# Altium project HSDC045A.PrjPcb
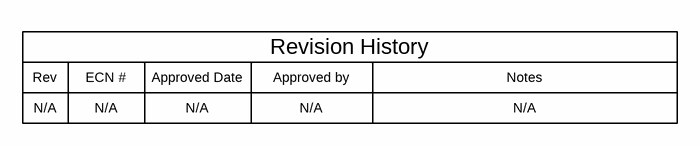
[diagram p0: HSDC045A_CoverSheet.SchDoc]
TID: N/A; TechSupport: https://e2e.ti.com/support/interface/ethernet/; SCH_Rev: A; PRJ_Title: DP83825EVM; PRJ_Number: HSDC045; PRJ_Engineer: Aniruddha Khadye; PRJ_Customer: Public Release; PCB_Rev: A; PCB_Layout: TBD; CopyrightYear: 2018
5 sheets, 159 parts. Net scope: global (net labels, ports and power ports of the same name join across sheets).
Board file: HSDC045A.PcbDoc
Sheets:
  HSDC045A_CoverSheet.SchDoc
  HSDC045A_Power.SchDoc
  HSDC045A_DP83825.SchDoc
  HSDC045A_Coms.SchDoc
  HSDC045A_Hardware.SchDoc

## Sheet HSDC045A_CoverSheet.SchDoc: Block Diagram
size 431 x 279 mm; Date: Not shown in title block; ApprovedBy: Not shown in title block; CheckedBy: Not shown in title block; Author: Not shown in title block; CompanyName: Not shown in title block; DrawnBy: Aniruddha Khadye; Engineer: Not shown in title block; Organization: Not shown in title block; Address1: Not shown in title block; Address2: Not shown in title block; Address3: Not shown in title block; Address4: Not shown in title block; DocumentNumber: 1; Revision: Use project parameter SCH_Rev; SheetNumber: 1; SheetTotal: 5; PageSetup: Record=PageOptions¦CenterHorizontal=True¦CenterVertical=True¦PrintScale=1.00¦XCorrection=1.00¦YCorrection=1.00¦PrintKind=0¦BorderSize=5000000¦LeftOffset=0¦BottomOffset=0¦Orientation=2¦PaperLength=1000¦PaperWidth=1000¦Scale=100¦PaperSource=15¦PrintQuality=600¦MediaType=1¦DitherType=10¦PaperKind=Letter¦PrintScaleMode=1

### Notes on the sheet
- Rev
- N/A
- ECN #
- Approved Date
- Approved by
- Revision History
- Notes

## Sheet HSDC045A_Power.SchDoc
size 431 x 279 mm; Date: Not shown in title block; ApprovedBy: Not shown in title block; CheckedBy: Not shown in title block; Author: Not shown in title block; CompanyName: Not shown in title block; Engineer: Not shown in title block; Organization: Not shown in title block; Address1: Not shown in title block; Address2: Not shown in title block; Address3: Not shown in title block; Address4: Not shown in title block; DocumentNumber: 2; Revision: Use project parameter SCH_Rev; SheetNumber: 2; SheetTotal: 5; PageSetup: Record=PageOptions¦CenterHorizontal=True¦CenterVertical=True¦PrintScale=1.00¦XCorrection=1.00¦YCorrection=1.00¦PrintKind=0¦BorderSize=5000000¦LeftOffset=0¦BottomOffset=0¦Orientation=2¦PaperLength=1000¦PaperWidth=1000¦Scale=100¦PaperSource=15¦PrintQuality=600¦MediaType=1¦DitherType=10¦PaperKind=Letter¦PrintScaleMode=1
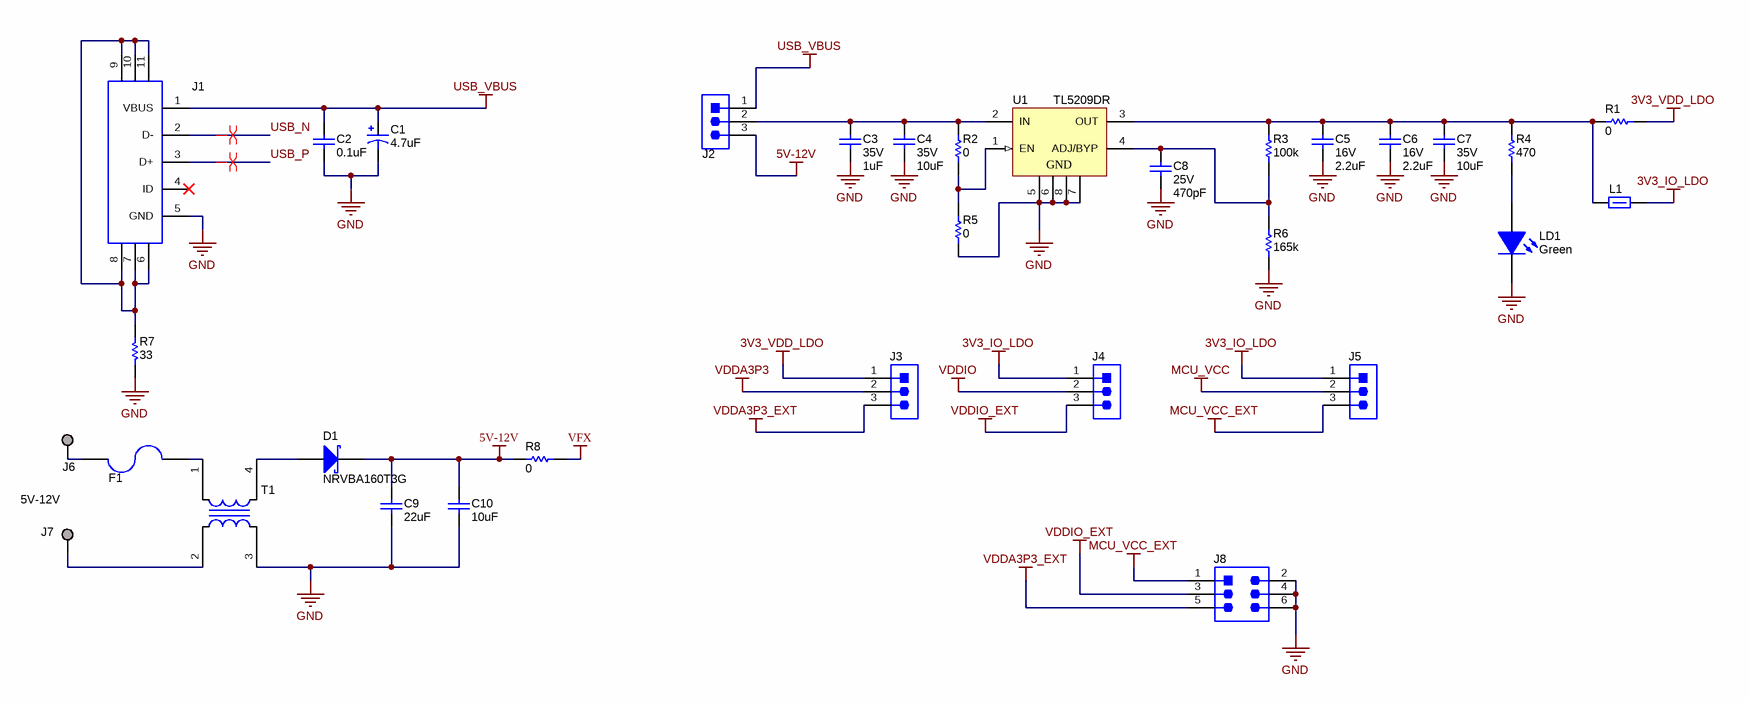
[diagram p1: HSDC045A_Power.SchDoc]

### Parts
C1  ValueDisplayed: 4.7uF  [7343-31]  (hidden comment: 293D475X9035D2TE3)
C2  ValueDisplayed: 0.1uF  [0402]  (hidden comment: GRM155R71C104KA88D)
C3  VDC_V: 35V  ValueDisplayed: 1uF  [0402]  (hidden comment: GRM155R6YA105ME11D)
C4  VDC_V: 35V  ValueDisplayed: 10uF  [0603]  (hidden comment: GRM188R6YA106MA73)
C5  VDC_V: 16V  ValueDisplayed: 2.2uF  [0402]  (hidden comment: GRM155C81C225KE11D)
C6  VDC_V: 16V  ValueDisplayed: 2.2uF  [0402]  (hidden comment: GRM155C81C225KE11D)
C7  VDC_V: 35V  ValueDisplayed: 10uF  [0603]  (hidden comment: GRM188R6YA106MA73)
C8  VDC_V: 25V  ValueDisplayed: 470pF  [0402]  (hidden comment: GRM1555C1E471JA01D)
C9  ValueDisplayed: 22uF  [1210_280]  (hidden comment: CGA6P1X7R1C226M250AC)
C10  ValueDisplayed: 10uF  [1210_280]  (hidden comment: CGA6P1X7R1E106M250AC)
D1  NRVBA160T3G  [SMA]
F1  F0603E3R00FSTR  [0603]  (value not drawn)
J1  475890001  [Molex_0475890001]  (value not drawn)
J2  PEC03SAAN  [CONN_PEC03SAAN]  (value not drawn)
J3  PEC03SAAN  [CONN_PEC03SAAN]  (value not drawn)
J4  PEC03SAAN  [CONN_PEC03SAAN]  (value not drawn)
J5  PEC03SAAN  [CONN_PEC03SAAN]  (value not drawn)
J6  1502-2  [Keystone1502-2]  (value not drawn)
J7  1502-2  [Keystone1502-2]  (value not drawn)
J8  5-146254-3  [TE_5-146254-3]  (value not drawn)
L1  BLM18AG102SN1D  [0603]  (value not drawn)
LD1  value Green  [QTLP630C_Green]  (hidden comment: QTLP630C4TR)
R1  ValueDisplayed: 0  [0603]  (hidden comment: ERJ-3GEY0R00V)
R2  ValueDisplayed: 0  [0603]  (hidden comment: ERJ-3GEY0R00V)
R3  ValueDisplayed: 100k  [0402]  (hidden comment: CRCW0402100KDHEDP)
R4  ValueDisplayed: 470  [0402]  (hidden comment: CRCW0402470RJNED)
R5  ValueDisplayed: 0  [0603]  (hidden comment: ERJ-3GEY0R00V)
R6  ValueDisplayed: 165k  [0402]  (hidden comment: CRCW0402165KFKED)
R7  ValueDisplayed: 33  [0402]  (hidden comment: CRCW040233R0JNED)
R8  ValueDisplayed: 0  [0402]  (hidden comment: MCR01MZPJ000)
T1  ACM9070-701-2PL-TL01  [TDK_ACM9070]  (value not drawn)
U1  TL5209DR  [D0008A_N]

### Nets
3V3_IO_LDO: J4.1 J5.1 L1.2
3V3_VDD_LDO: J3.1 R1.2
5V-12V: C9.1 C10.1 D1.1(K) J2.3 R8.2
GND: C1.2(-) C2.1 C3.2 C4.2 C5.2 C6.2 C7.2 C8.2 C9.2 C10.2 J1.5(GND) J8.2 J8.4 J8.6 LD1.2(K) R5.1 R6.1 R7.2 T1.3 U1.5(GND) U1.6(GND) U1.7(GND) U1.8(GND)
MCU_VCC: J5.2
MCU_VCC_EXT: J5.3 J8.1
USB_VBUS: C1.1(+) C2.2 J1.1(VBUS) J2.1
VDDA3P3: J3.2
VDDA3P3_EXT: J3.3 J8.5
VDDIO: J4.2
VDDIO_EXT: J4.3 J8.3
VFX: R8.1
USB_N: J1.2(D-)
USB_P: J1.3(D+)
NetC3_1: C3.1 C4.1 J2.2 R2.2 U1.2(IN)
NetC5_1: C5.1 C6.1 C7.1 L1.1 R1.1 R3.2 R4.2 U1.3(OUT)
NetC8_1: C8.1 R3.1 R6.2 U1.4(ADJ/BYP)
NetD1_2: D1.2(A) T1.4
NetF1_1: F1.1 J6.1
NetF1_2: F1.2 T1.1
NetJ1_6: J1.6 J1.7 J1.8 J1.9 J1.10 J1.11 R7.1
NetJ7_1: J7.1 T1.2
NetLD1_1: LD1.1(A) R4.1
NetR2_1: R2.1 R5.2 U1.1(EN)

Not connected (* = marked no-connect by the designer): J1 4(ID)*

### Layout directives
differential pair: USB_N, USB_P

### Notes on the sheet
- 5V-12V

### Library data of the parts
C1 = CMP-0011708-2: CAP, TA, 4.7 uF, 35 V, +/- 10%, 1.3 ohm, SMD; Manufacturer: Vishay-Sprague; Polarized: Y; CompType: Capacitor; Value: 4.7uF; U/M: EA; Cap_F: 4.7µF; Value1: 1.3 ohm; VDC_V: 35V; ESR_ohm: 1.3; IRMS_A: 3.4dA; TaMin_C: -55°C; TaMax_C: 125°C; Cap_Case: D; AEC Category: Q200; SizeAreaWB_mm2: 58.59; SizeArea_mm2: 31.39; SizeX_mm: 7.3; SizeY_mm: 4.3; SizeZ_mm: 3.1
C2 = CMP-0006641-2: CAP, CERM, 0.1 uF, 16 V, +/- 10%, X7R, 0402; Manufacturer: MuRata; Polarized: N; Value: 0.1uF; U/M: EA; Cap_F: 100nF; Value1: Unknown; VDC_V: 16V; TaMin_C: -55°C; TaMax_C: 125°C; AEC Category: Q200; SizeArea_mm2: 0.5; SizeAreaWB_mm2: 3; SizeX_mm: 1; SizeZ_mm: 0.6
C3 = CMP-0006620-2: CAP, CERM, 1 uF, 35 V, +/- 20%, X5R, 0402; Manufacturer: MuRata; TaMin_C: -55°C; Polarized: N; SizeAreaWB_mm2: 3; Value1: Unknown; U/M: EA; Value: 1uF; TaMax_C: 85°C; SizeZ_mm: 0.6; SizeX_mm: 1; SizeY_mm: 0.5; Cap_F: 1µF; AEC Category: Q200
C4 C7 = CMP-0007355-5: CAP, CERM, 10 uF, 35 V, +/- 20%, X5R, 0603; Manufacturer: Nichicon; TaMin_C: -55°C; Polarized: N; SizeAreaWB_mm2: 4.68; Value1: Unknown; U/M: EA; Value: 10uF; TaMax_C: 85°C; SizeZ_mm: 1; SizeX_mm: 1.6; SizeY_mm: 0.8; SizeArea_mm2: 1.28; Cap_F: 10µF; AEC Category: Q200
C5 C6 = CMP-0006526-2: CAP, CERM, 2.2 uF, 16 V, +/- 10%, X6S, 0402; Manufacturer: MuRata; TaMin_C: -55°C; Polarized: N; SizeAreaWB_mm2: 3; Value1: Unknown; U/M: EA; Value: 2.2uF; TaMax_C: 105°C; SizeZ_mm: 0.6; SizeX_mm: 1; SizeY_mm: 0.5; Cap_F: 2.2µF; AEC Category: Q200
C8 = CMP-0006389-2: CAP, CERM, 470 pF, 25 V, +/- 5%, C0G/NP0, 0402; Manufacturer: MuRata; TaMin_C: -55°C; Polarized: N; SizeAreaWB_mm2: 3; Value1: Unknown; U/M: EA; Value: 470pF; TaMax_C: 125°C; SizeZ_mm: 0.6; SizeX_mm: 1; SizeY_mm: 0.5; AEC Category: Q200
C9 = CMP-0009154-2: CAP, CERM, 22 uF, 16 V, +/- 20%, X7R, AEC-Q200 Grade 1, 1210; Manufacturer: TDK; Polarized: N; Value: 22uF; U/M: EA; Cap_F: 22µF; ESR_ohm: 2.582m; Value1: 0.002582 ohm; VDC_V: 16V; IRMS_A: 4.57562A; TaMin_C: -55°C; TaMax_C: 125°C; AEC Category: Q200; AEC Qualified: Y; AEC Grade: 1; SizeArea_mm2: 8; SizeAreaWB_mm2: 14.7; SizeX_mm: 3.2; SizeY_mm: 2.5; SizeZ_mm: 2.8
C10 = CMP-0009155-2: CAP, CERM, 10 uF, 25 V, +/- 20%, X7R, AEC-Q200 Grade 1, 1210; Manufacturer: TDK; Polarized: N; Value: 10uF; U/M: EA; Cap_F: 10µF; Value1: Unknown; VDC_V: 25V; TaMin_C: -55°C; TaMax_C: 125°C; Cap_Case: 1210; AEC Category: Q200; AEC Qualified: Y; AEC Grade: 1; SizeArea_mm2: 8; SizeAreaWB_mm2: 14.7; SizeX_mm: 3.2; SizeY_mm: 2.5; SizeZ_mm: 2.8
D1 = CMP-0028762-1: Diode, Schottky, 60 V, 1 A, AEC-Q101, SMA; Manufacturer: ON Semiconductor; U/M: EA; Vf_V: 5.1dV; Value: 60V; Value1: 1A; Value2: 0.51V; TJmax_C: 150°C; AEC Category: Q101; AEC Qualified: Y; Green_Lifecycle: Active; Green_REACh: Passed; SizeArea_mm2: 16.3228; SizeAreaWB_mm2: 37.3428; SizeX_mm: 5.59; SizeY_mm: 2.92; SizeZ_mm: 2.87
F1 = CMP-0003588-3: Fuse, 3 A, 32 VDC, SMD; Manufacturer: AVX; VDC_V: 32V; Irating_A: 3A; Rtyp_Ohm: 0.03; SizeAreaWB_mm2: 4.68; SizeArea_mm2: 1.28; SizeX_mm: 1.6; SizeY_mm: 0.8; SizeZ_mm: 1
J1 = CMP-0055301-1: Connector, Receptacle, Micro-USB Type AB, R/A, Bottom Mount SMT; Manufacturer: Molex; CompType: USB; Gender: Female; CNHeader: FALSE; CT: TRUE; Green_Lifecycle: Active; Green_REACh: Passed
J2-J5 = CMP-0002338-1: Header, 100mil, 3x1, Tin, TH; Manufacturer: Sullins Connector Solutions; CNHeader: TRUE; Current_A: 3A; Green_Lifecycle: Not Set; Shrouded: N; Gender: Male; Green_REACh: Incomplete; Voltage_V: 1.8kV; Row_Count: 1; Pitch_mm: 2.54; CT: FALSE; Cert_UL: Y
J6 J7 = CMP-0055113-1: Terminal, Turret, TH, Double; Manufacturer: Keystone; CompType: Turret Terminal; CNHeader: FALSE; Green_Lifecycle: Active; Green_REACh: Passed
J8 = CMP-0054953-2: Header, 100mil, 3x2, Tin, TH; Manufacturer: TE Connectivity; Green_REACh: Passed; Green_Lifecycle: Active
L1 = CMP-0003343-2: Ferrite Bead, 1000 ohm @ 100 MHz, 0.4 A, 0603; Manufacturer: MuRata; ZTyp@100MHz_Ohm: 1k; SizeAreaWB_mm2: 4.68; DCR_ohm: 5d; Value1: 0.5 ohm; Imax_A: 4dA; SizeZ_mm: 1; SizeX_mm: 1.6; SizeY_mm: 0.8; Value2: 0.4A; SizeArea_mm2: 1.28
LD1 = CMP-0002917-1: LED, Green, SMD; Manufacturer: Everlight; Vf_V: 2.1V; Io_A: 20mA; Vr_V: 5V; Tjmax_C: 85°C; Value1: W; Angle: 140; U/M: EA
R1 R2 R5 = CMP-0025874-4: RES, 0, 5%, 0.1 W, AEC-Q200 Grade 0, 0603; Manufacturer: Panasonic; Power_W: 100mW; TempCo: 600 ppm/C; Value_Code: 0000; Value: 0; EIA_Code: E24; SizeX_mm: 1.6; SizeY_mm: 0.8; SizeZ_mm: 1; Value2: 0.1W; SizeArea_mm2: 1.28; AEC Qualified: Y; VDC_V: 50V; AEC Category: Q200; SizeAreaWB_mm2: 4.68
R3 = CMP-0026768-2: RES, 100 k, 0.5%, 0.063 W, AEC-Q200 Grade 0, 0402; Manufacturer: Vishay-Dale; Power_W: 63mW; TempCo: 50 ppm/C; Value: 100k; EIA_Code: E192; SizeX_mm: 1; SizeY_mm: 0.5; SizeZ_mm: 0.6; Value2: 0.063W; AEC Qualified: Y; VDC_V: 50V; AEC Category: Q200; AEC Grade: 0
R4 = CMP-0026934-3: RES, 470, 5%, 0.063 W, AEC-Q200 Grade 0, 0402; Manufacturer: Vishay-Dale; Power_W: 63mW; TempCo: 200 ppm/C; Value_Code: 470R; Value: 470; EIA_Code: E24; SizeX_mm: 1; SizeY_mm: 0.5; SizeZ_mm: 0.6; Value2: 0.063W; AEC Qualified: Y; VDC_V: 50V; AEC Category: Q200; AEC Grade: 0
R6 = CMP-0026036-3: RES, 165 k, 1%, 0.063 W, AEC-Q200 Grade 0, 0402; Manufacturer: Vishay-Dale; Power_W: 63mW; TempCo: 100 ppm/C; Value: 165k; EIA_Code: E96; SizeX_mm: 1; SizeY_mm: 0.5; SizeZ_mm: 0.6; Value2: 0.063W; AEC Qualified: Y; VDC_V: 50V; AEC Category: Q200; AEC Grade: 0
R7 = CMP-0026908-3: RES, 33, 5%, 0.063 W, AEC-Q200 Grade 0, 0402; Manufacturer: Vishay-Dale; Value: 33; Value_Code: 33R0; Power_W: 63mW; Value2: 0.063W; VDC_V: 50V; TempCo: 200 ppm/C; EIA_Code: E24; AEC Category: Q200; AEC Qualified: Y; AEC Grade: 0; SizeArea_mm2: 0.5; SizeX_mm: 1; SizeZ_mm: 0.6
R8 = CMP-0027002-2: RES, 0, 5%, 0.063 W, 0402; Manufacturer: Rohm; Power_W: 63mW; TempCo: 500 ppm/C; Value_Code: 0000; U/M: EA; Value: 0; EIA_Code: E24; SizeX_mm: 1; SizeY_mm: 0.5; SizeZ_mm: 0.6; Value2: 0.063W; VDC_V: 50V; AEC Category: Q200
T1 = CMP-0013076-2: Coupled inductor, 5 A, 0.01 ohm, SMD; Manufacturer: TDK; DCR_ohm: 0.01
U1 = CMP-0036447-1: Single Output Low Noise LDO, 500 mA, Adjustable 1.3 to 6.5 V Output, 2.5 to 16 V Input, 8-pin SOIC (D), -40 to 125 degC, Green (RoHS & no Sb/Br); Manufacturer: Texas Instruments; Iq(Typ)(mA): 8; Accuracy(%): 2; Vdo(Typ)(mV): 500; Iout(Max)(A): 0.5; Vin(Max)(V): 16; Vout Adj(Min)(V): 2.5; Vout Adj(Max)(V): 6.5; SubFamily: Single Channel LDO; Rating: Catalog

## Sheet HSDC045A_DP83825.SchDoc: DP83825
size 431 x 279 mm; Date: Not shown in title block; ApprovedBy: Not shown in title block; CheckedBy: Not shown in title block; Author: Not shown in title block; CompanyName: Not shown in title block; DrawnBy: Aniruddha Khadye; Engineer: Not shown in title block; Organization: Not shown in title block; Address1: Not shown in title block; Address2: Not shown in title block; Address3: Not shown in title block; Address4: Not shown in title block; DocumentNumber: 3; Revision: Use project parameter SCH_Rev; SheetNumber: 3; SheetTotal: 5; PageSetup: Record=PageOptions¦CenterHorizontal=True¦CenterVertical=True¦PrintScale=1.00¦XCorrection=1.00¦YCorrection=1.00¦PrintKind=0¦BorderSize=5000000¦LeftOffset=0¦BottomOffset=0¦Orientation=2¦PaperLength=1000¦PaperWidth=1000¦Scale=100¦PaperSource=15¦PrintQuality=600¦MediaType=1¦DitherType=10¦PaperKind=Letter¦PrintScaleMode=1
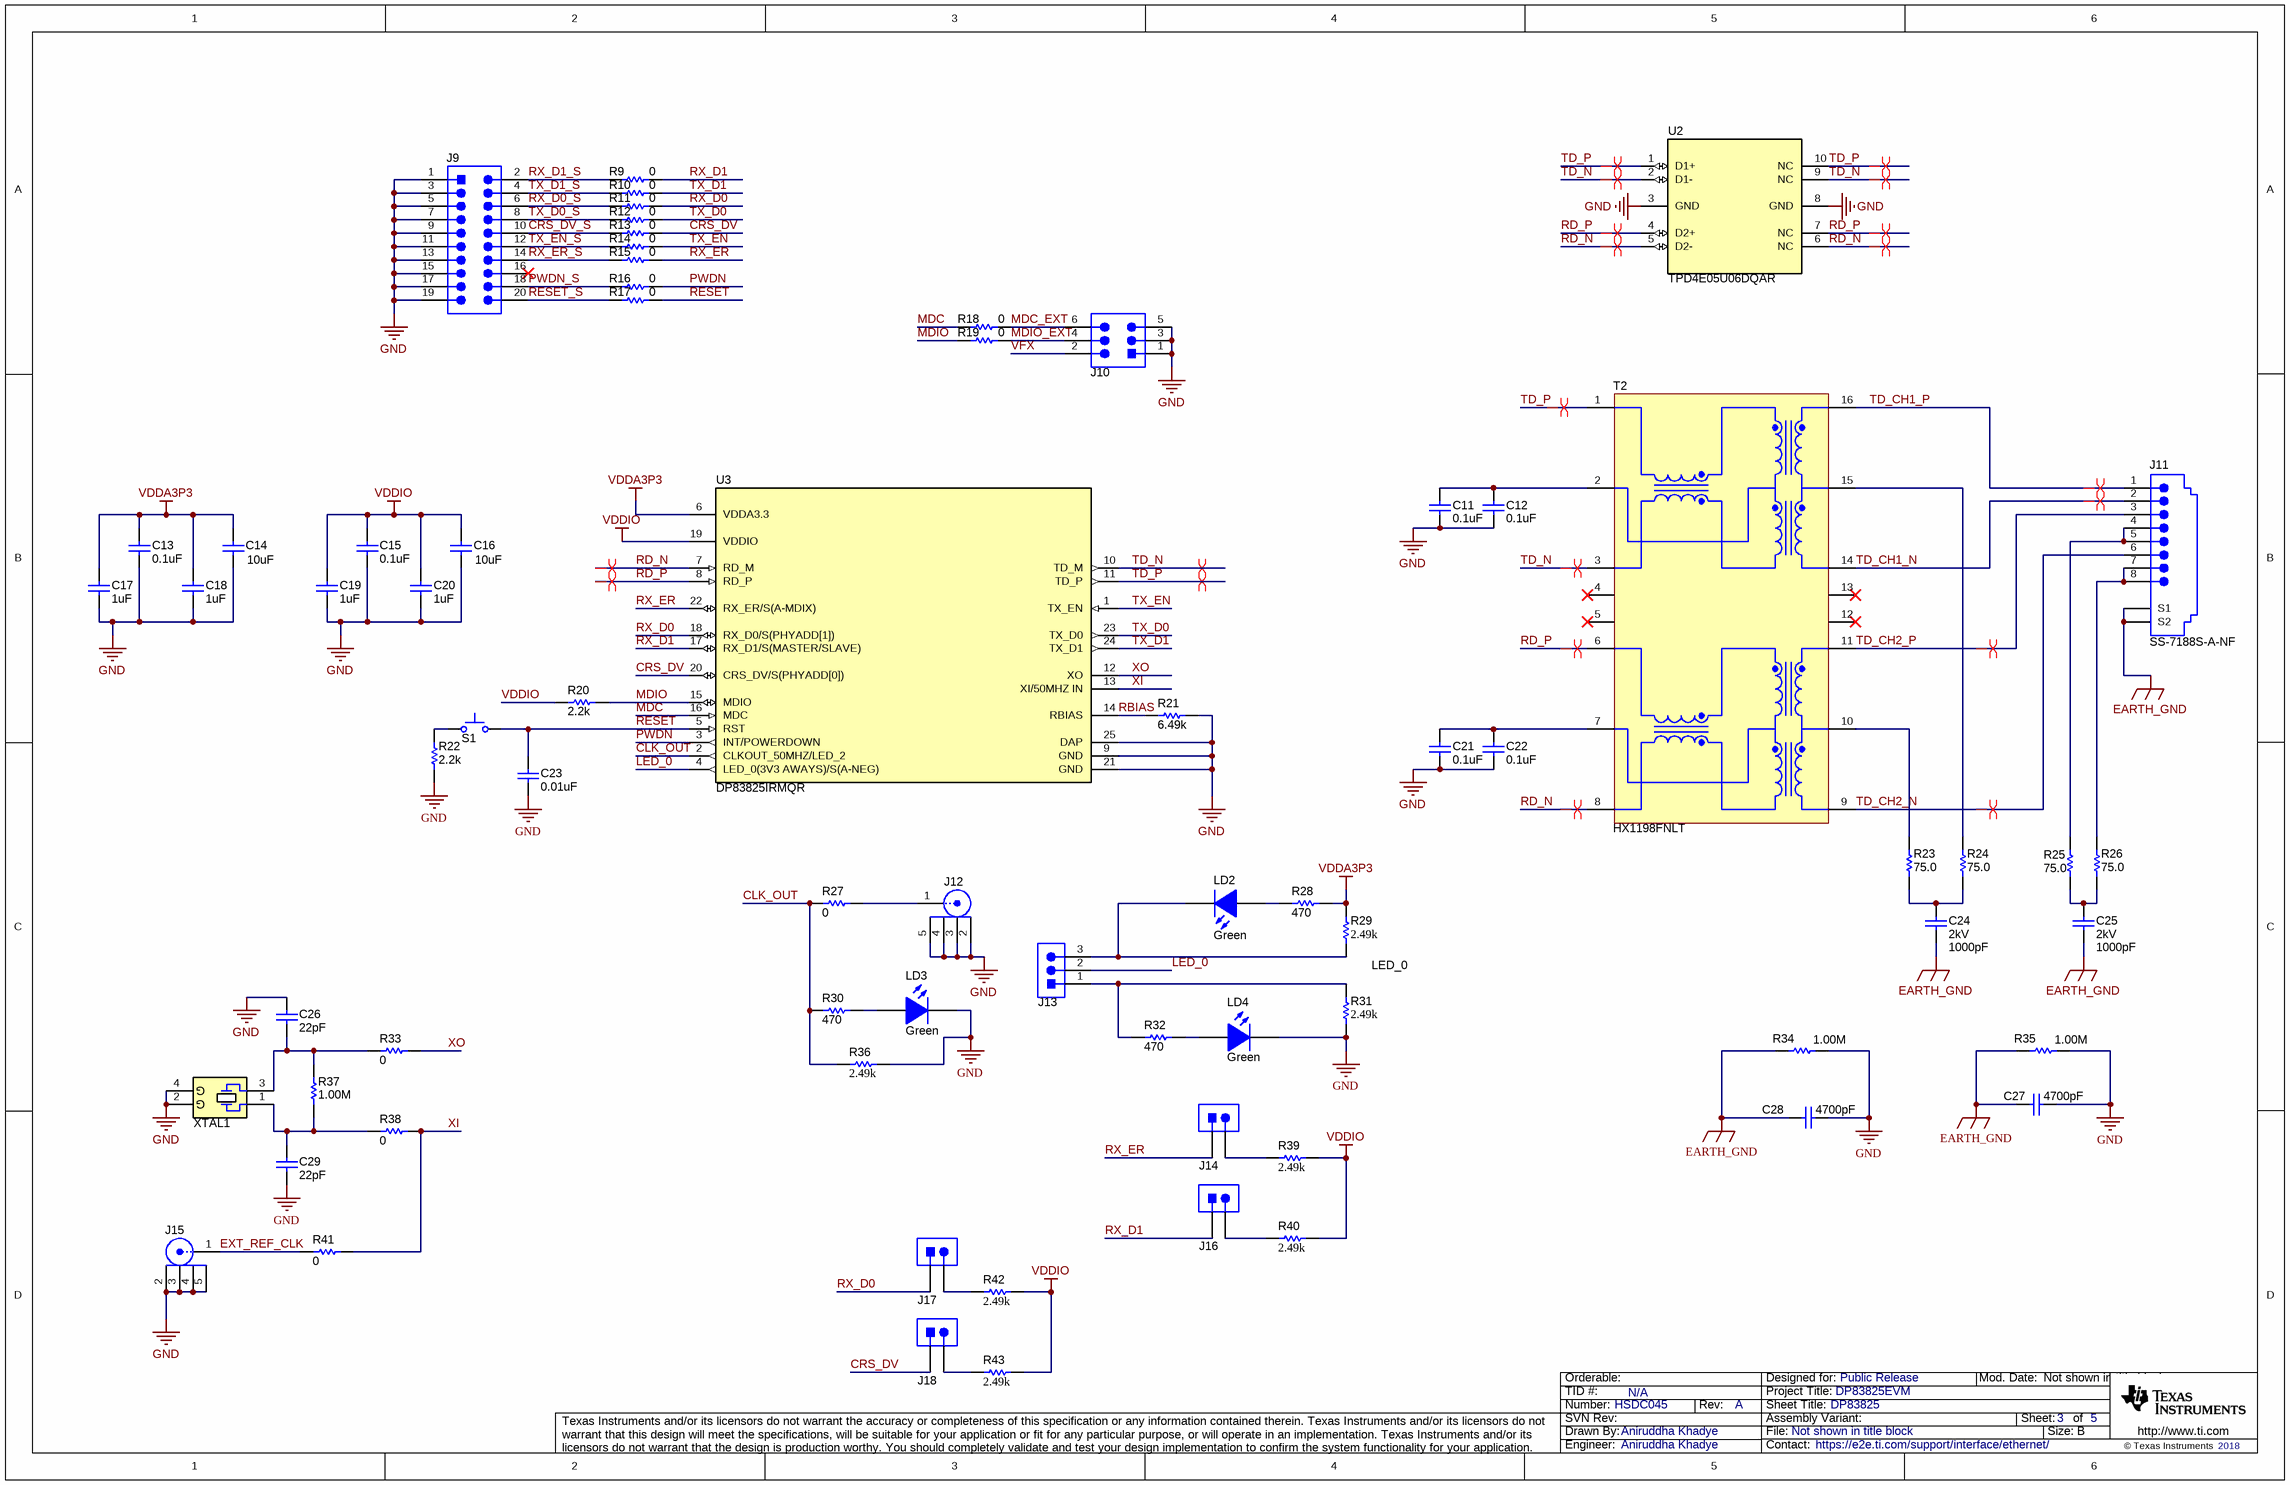
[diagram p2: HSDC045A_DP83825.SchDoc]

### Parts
C11  ValueDisplayed: 0.1uF  [0603]  (hidden comment: C0603C104K8RACTU)
C12  ValueDisplayed: 0.1uF  [0603]  (hidden comment: C0603C104K8RACTU)
C13  ValueDisplayed: 0.1uF  [0402]  (hidden comment: C1005X5R1A104K050BA)
C14  ValueDisplayed: 10uF  [0402]  (hidden comment: GRM155R60J106ME11)
C15  ValueDisplayed: 0.1uF  [0402]  (hidden comment: C1005X5R1A104K050BA)
C16  ValueDisplayed: 10uF  [0402]  (hidden comment: GRM155R60J106ME11)
C17  ValueDisplayed: 1uF  [0402]  (hidden comment: GRM155R61A105KE15D)
C18  ValueDisplayed: 1uF  [0402]  (hidden comment: GRM155R61A105KE15D)
C19  ValueDisplayed: 1uF  [0402]  (hidden comment: GRM155R61A105KE15D)
C20  ValueDisplayed: 1uF  [0402]  (hidden comment: GRM155R61A105KE15D)
C21  ValueDisplayed: 0.1uF  [0603]  (hidden comment: C0603C104K8RACTU)
C22  ValueDisplayed: 0.1uF  [0603]  (hidden comment: C0603C104K8RACTU)
C23  ValueDisplayed: 0.01uF  [0402L]  (hidden comment: GRM155R71H103KA88D)
C24  VDC_V: 2kV  ValueDisplayed: 1000pF  [1808]  (hidden comment: GR442QR73D102KW01L)
C25  VDC_V: 2kV  ValueDisplayed: 1000pF  [1808]  (hidden comment: GR442QR73D102KW01L)
C26  ValueDisplayed: 22pF  [0603]  (hidden comment: CGA3E2C0G1H220J080AA)
C27  ValueDisplayed: 4700pF  [1812_254]  (hidden comment: 1812GC472KAT1A)
C28  ValueDisplayed: 4700pF  [1812_254]  (hidden comment: 1812GC472KAT1A)
C29  ValueDisplayed: 22pF  [0603]  (hidden comment: CGA3E2C0G1H220J080AA)
J9  PRPC010DAAN-RC  [Sullins_xxxC010DAAN]  (value not drawn)
J10  90122-0763  [Molex_90122-0763]  (value not drawn)
J11  SS-7188S-A-NF  [Stewart_SS-7188S-A-NF]
J12  5-1814400-1  [TE_5-1814400-1]  (value not drawn)
J13  HTSW-103-07-G-S  [Samtec_HTSW-103-07-G-S]  (value not drawn)
J14  HTSW-102-07-G-S  [Samtec_HTSW-102-07-G-S]  (value not drawn)
J15  5-1814832-1  [TE_5-1814832-1]  (value not drawn)
J16  HTSW-102-07-G-S  [Samtec_HTSW-102-07-G-S]  (value not drawn)
J17  HTSW-102-07-G-S  [Samtec_HTSW-102-07-G-S]  (value not drawn)
J18  HTSW-102-07-G-S  [Samtec_HTSW-102-07-G-S]  (value not drawn)
LD2  value Green  [QTLP630C_Green]  (hidden comment: QTLP630C4TR)
LD3  value Green  [QTLP630C_Green]  (hidden comment: QTLP630C4TR)
LD4  value Green  [QTLP630C_Green]  (hidden comment: QTLP630C4TR)
R9  ValueDisplayed: 0  [0402]  (hidden comment: CRCW04020000Z0ED)
R10  ValueDisplayed: 0  [0402]  (hidden comment: CRCW04020000Z0ED)
R11  ValueDisplayed: 0  [0402]  (hidden comment: CRCW04020000Z0ED)
R12  ValueDisplayed: 0  [0402]  (hidden comment: CRCW04020000Z0ED)
R13  ValueDisplayed: 0  [0402]  (hidden comment: CRCW04020000Z0ED)
R14  ValueDisplayed: 0  [0402]  (hidden comment: CRCW04020000Z0ED)
R15  ValueDisplayed: 0  [0402]  (hidden comment: CRCW04020000Z0ED)
R16  ValueDisplayed: 0  [0402]  (hidden comment: CRCW04020000Z0ED)
R17  ValueDisplayed: 0  [0402]  (hidden comment: CRCW04020000Z0ED)
R18  ValueDisplayed: 0  [0402]  (hidden comment: CRCW04020000Z0ED)
R19  ValueDisplayed: 0  [0402]  (hidden comment: CRCW04020000Z0ED)
R20  ValueDisplayed: 2.2k  [0402]  (hidden comment: CRCW04022K20JNED)
R21  ValueDisplayed: 6.49k  [0402]  (hidden comment: CRCW04026K49FKED)
R22  ValueDisplayed: 2.2k  [0201M]  (hidden comment: CRCW02012K20JNED)
R23  ValueDisplayed: 75.0  [0805_HV]  (hidden comment: CRCW080575R0FKEA)
R24  ValueDisplayed: 75.0  [0805_HV]  (hidden comment: CRCW080575R0FKEA)
R25  ValueDisplayed: 75.0  [0805_HV]  (hidden comment: CRCW080575R0FKEA)
R26  ValueDisplayed: 75.0  [0805_HV]  (hidden comment: CRCW080575R0FKEA)
R27  ValueDisplayed: 0  [0402]  (hidden comment: CRCW04020000Z0ED)
R28  ValueDisplayed: 470  [0402]  (hidden comment: CRCW0402470RJNED)
R29  ValueDisplayed: 2.49k  [0402]  (hidden comment: CRCW04022K49FKED)
R30  ValueDisplayed: 470  [0402]  (hidden comment: CRCW0402470RJNED)
R31  ValueDisplayed: 2.49k  [0402]  (hidden comment: CRCW04022K49FKED)
R32  ValueDisplayed: 470  [0402]  (hidden comment: CRCW0402470RJNED)
R33  ValueDisplayed: 0  [0201M]  (hidden comment: ERJ-1GE0R00C)
R34  ValueDisplayed: 1.00M  [2010]  (hidden comment: HVCB2010FKC1M00)
R35  ValueDisplayed: 1.00M  [2010]  (hidden comment: HVCB2010FKC1M00)
R36  ValueDisplayed: 2.49k  [0402]  (hidden comment: CRCW04022K49FKED)
R37  ValueDisplayed: 1.00M  [0402]  (hidden comment: RC0402FR-071ML)
R38  ValueDisplayed: 0  [0201M]  (hidden comment: ERJ-1GE0R00C)
R39  ValueDisplayed: 2.49k  [0402]  (hidden comment: CRCW04022K49FKED)
R40  ValueDisplayed: 2.49k  [0402]  (hidden comment: CRCW04022K49FKED)
R41  ValueDisplayed: 0  [0201]  (hidden comment: ERJ-1GE0R00C)
R42  ValueDisplayed: 2.49k  [0402]  (hidden comment: CRCW04022K49FKED)
R43  ValueDisplayed: 2.49k  [0402]  (hidden comment: CRCW04022K49FKED)
S1  KSR221GLFS  [KSR]  (value not drawn)
T2  HX1198FNLT  [Pulse_HX1198FNLT]
U2  TPD4E05U06DQAR  [DQA0010A]
U3  DP83825IRMQR  [RMQ0024A]
XTAL1  ECS-250-12-33Q-JES-TR  [ECS_ECS-33Q]  (value not drawn)

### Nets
EARTH_GND: C24.2 C25.2 C27.2 C28.2 J11.S1 J11.S2 R34.1 R35.1
GND: C11.2 C12.2 C13.2 C14.2 C15.2 C16.2 C17.2 C18.2 C19.2 C20.2 C21.2 C22.2 C23.1 C26.2 C27.1 C28.1 C29.2 J9.1 J9.3 J9.5 J9.7 J9.9 J9.11 J9.13 J9.15 J9.17 J9.19 J10.1 J10.3 J10.5 J12.2 J12.3 J12.4 J12.5 J15.2 J15.3 J15.4 J15.5 LD3.2(K) LD4.2(K) R21.2 R22.1 R31.1 R34.2 R35.2 R36.2 U2.3(GND) U2.8(GND) U3.9(GND) U3.21(GND) U3.25(DAP) XTAL1.2(GND) XTAL1.4(GND)
VDDA3P3: C13.1 C14.1 C17.1 C18.1 R28.2 R29.2 U3.6(VDDA3.3)
VDDIO: C15.1 C16.1 C19.1 C20.1 R20.2 R39.2 R40.2 R42.2 R43.2 U3.19(VDDIO)
VFX: J10.2
CLK_OUT: R27.1 R30.1 R36.1 U3.2(CLKOUT_50MHZ/LED_2)
CRS_DV: J18.1 R13.2 U3.20(CRS_DV/S(PHYADD[0]))
CRS_DV_S: J9.10 R13.1
EXT_REF_CLK: J15.1 R41.1
LED_0: J13.2 U3.4(LED_0(3V3_AWAYS)/S(A-NEG))
MDC: R18.1 U3.16(MDC)
MDC_EXT: J10.6 R18.2
MDIO: R19.1 R20.1 U3.15(MDIO)
MDIO_EXT: J10.4 R19.2
PWDN: R16.2 U3.3(INT/POWERDOWN)
PWDN_S: J9.18 R16.1
RBIAS: R21.1 U3.14(RBIAS)
RD_N: T2.8(RD-) U2.5(D2-) U2.6(NC) U3.7(RD_M)
RD_P: T2.6(RD+) U2.4(D2+) U2.7(NC) U3.8(RD_P)
RESET: C23.2 R17.2 S1.2 U3.5(RST)
RESET_S: J9.20 R17.1
RX_D0: J17.1 R11.2 U3.18(RX_D0/S(PHYADD[1]))
RX_D0_S: J9.6 R11.1
RX_D1: J16.1 R9.2 U3.17(RX_D1/S(MASTER/SLAVE))
RX_D1_S: J9.2 R9.1
RX_ER: J14.1 R15.2 U3.22(RX_ER/S(A-MDIX))
RX_ER_S: J9.14 R15.1
TD_CH1_N: J11.2 T2.14(TX-)
TD_CH1_P: J11.1 T2.16(TX+)
TD_CH2_N: J11.6 T2.9(RX-)
TD_CH2_P: J11.3 T2.11(RX+)
TD_N: T2.3(TD-) U2.2(D1-) U2.9(NC) U3.10(TD_M)
TD_P: T2.1(TD+) U2.1(D1+) U2.10(NC) U3.11(TD_P)
TX_D0: R12.2 U3.23(TX_D0)
TX_D0_S: J9.8 R12.1
TX_D1: R10.2 U3.24(TX_D1)
TX_D1_S: J9.4 R10.1
TX_EN: R14.2 U3.1(TX_EN)
TX_EN_S: J9.12 R14.1
XI: R38.2 R41.2 U3.13(XI/50MHZ_IN)
XO: R33.2 U3.12(XO)
NetC11_1: C11.1 C12.1 T2.2(TCT)
NetC21_1: C21.1 C22.1 T2.7(RCT)
NetC24_1: C24.1 R23.1 R24.1
NetC25_1: C25.1 R25.1 R26.1
NetC26_1: C26.1 R33.1 R37.2 XTAL1.3
NetC29_1: C29.1 R37.1 R38.1 XTAL1.1
NetJ11_4: J11.4 J11.5 R25.2
NetJ11_7: J11.7 J11.8 R26.2
NetJ12_1: J12.1 R27.2
NetJ13_1: J13.1 R31.2 R32.1
NetJ13_3: J13.3 LD2.2(K) R29.1
NetJ14_2: J14.2 R39.1
NetJ16_2: J16.2 R40.1
NetJ17_2: J17.2 R42.1
NetJ18_2: J18.2 R43.1
NetLD2_1: LD2.1(A) R28.1
NetLD3_1: LD3.1(A) R30.2
NetLD4_1: LD4.1(A) R32.2
NetR22_2: R22.2 S1.1
NetR23_2: R23.2 T2.10(CMT)
NetR24_2: R24.2 T2.15(CMT)

Not connected (* = marked no-connect by the designer): J9 16*; T2 4(NC)* 5(NC)* 12(NC)* 13(NC)*

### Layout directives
differential pair: RD_N, RD_P, TD_CH1_N, TD_CH1_P, TD_CH2_N, TD_CH2_P, TD_N, TD_P

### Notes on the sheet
- LED_0

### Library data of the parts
C11 C12 C21 C22 = CMP-0006862-5: CAP, CERM, 0.1 uF, 10 V, +/- 10%, X7R, 0603; Manufacturer: Kemet; TaMin_C: -55°C; Polarized: N; SizeAreaWB_mm2: 4.68; Value1: Unknown; U/M: EA; Value: 0.1uF; TaMax_C: 125°C; SizeZ_mm: 1; SizeX_mm: 1.6; SizeY_mm: 0.8; Value2: 10V; SizeArea_mm2: 1.28; Cap_F: 100nF; AEC Category: Q200
C13 C15 = CMP-0006259-2: CAP, CERM, 0.1 uF, 10 V, +/- 10%, X5R, 0402; Manufacturer: TDK; Polarized: N; Value: 0.1uF; U/M: EA; Cap_F: 100nF; Value1: Unknown; VDC_V: 10V; TaMin_C: -55°C; TaMax_C: 85°C; AEC Category: Q200; SizeArea_mm2: 0.5; SizeAreaWB_mm2: 3; SizeX_mm: 1; SizeZ_mm: 0.6
C14 C16 = CMP-0006533-2: CAP, CERM, 10 uF, 6.3 V, +/- 20%, X5R, 0402; Manufacturer: MuRata; TaMin_C: -55°C; Polarized: N; SizeAreaWB_mm2: 3; Value1: Unknown; U/M: EA; Value: 10uF; TaMax_C: 85°C; SizeZ_mm: 0.6; SizeX_mm: 1; SizeY_mm: 0.5; Value2: 6.3V; CompType: Capacitor; Cap_F: 10µF; AEC Category: Q200
C17 C19 = CMP-0006563-2: CAP, CERM, 1 uF, 10 V, +/- 10%, X5R, 0402; Manufacturer: MuRata; Polarized: N; Value: 1uF; U/M: EA; Cap_F: 1µF; Value1: Unknown; VDC_V: 10V; TaMin_C: -55°C; TaMax_C: 85°C; AEC Category: Q200; SizeArea_mm2: 0.5; SizeAreaWB_mm2: 3; SizeX_mm: 1; SizeZ_mm: 0.6
C18 C20 = CMP-0006563-2: CAP, CERM, 1 uF, 10 V, +/- 10%, X5R, 0402; Manufacturer: MuRata; Polarized: N; CompType: Capacitor; Value: 1uF; U/M: EA; Cap_F: 1µF; Value1: Unknown; VDC_V: 10V; TaMin_C: -55°C; TaMax_C: 85°C; AEC Category: Q200; SizeArea_mm2: 0.5; SizeAreaWB_mm2: 3; SizeX_mm: 1; SizeZ_mm: 0.6
C23 = CMP-0006674-2: CAP, CERM, 0.01 uF, 50 V, +/- 10%, X7R, 0402; Manufacturer: MuRata; Polarized: N; Value: 0.01uF; U/M: EA; Cap_F: 10nF; Value1: Unknown; VDC_V: 50V; TaMin_C: -55°C; TaMax_C: 125°C; Cap_Case: 0402; AEC Category: Q200; SizeArea_mm2: 0.5; SizeAreaWB_mm2: 3; SizeX_mm: 1; SizeZ_mm: 0.6
C24 C25 = CMP-0009436-2: CAP, CERM, 1000 pF, 2000 V, +/- 10%, X7R, 1808; Manufacturer: MuRata; TaMin_C: -55°C; Polarized: N; SizeAreaWB_mm2: 16.5; Value1: Unknown; U/M: EA; Value: 1000pF; TaMax_C: 125°C; SizeZ_mm: 2.03; SizeX_mm: 4.5; SizeY_mm: 2; Value2: 2000V; SizeArea_mm2: 9; Cap_F: 1nF; AEC Category: Q200
C26 C29 = CMP-0007071-4: CAP, CERM, 22 pF, 50 V, +/- 5%, C0G/NP0, AEC-Q200 Grade 1, 0603; Manufacturer: TDK; Polarized: N; Value: 22pF; U/M: EA; Value1: Unknown; VDC_V: 50V; TaMin_C: -55°C; TaMax_C: 125°C; SizeArea_mm2: 1.28; SizeAreaWB_mm2: 4.68; SizeX_mm: 1.6; SizeY_mm: 0.8; SizeZ_mm: 1; AEC Category: Q200; AEC Qualified: Y
C27 = CMP-0009295-2: CAP, CERM, 4700 pF, 2000 V, +/- 10%, X7R, 1812; Manufacturer: AVX; Polarized: N; Value: 4700pF; U/M: EA; Cap_F: 4.7nF; Value1: Unknown; VDC_V: 2kV; Value2: 2000V; TaMin_C: -55°C; TaMax_C: 125°C; Cap_Case: 1812; AEC Category: Q200; SizeArea_mm2: 14.4; SizeAreaWB_mm2: 23.1; SizeX_mm: 4.5; SizeY_mm: 3.2; SizeZ_mm: 2.54
C28 = CMP-0009295-2: CAP, CERM, 4700 pF, 2000 V, +/- 10%, X7R, 1812; Manufacturer: AVX; Polarized: N; CompType: Capacitor; Value: 4700pF; U/M: EA; Cap_F: 4.7nF; Value1: Unknown; VDC_V: 2kV; Value2: 2000V; TaMin_C: -55°C; TaMax_C: 125°C; Cap_Case: 1812; AEC Category: Q200; SizeArea_mm2: 14.4; SizeAreaWB_mm2: 23.1; SizeX_mm: 4.5; SizeY_mm: 3.2; SizeZ_mm: 2.54
J9 = CMP-0054591-2: Header, 2.54mm, 10x2, Gold, TH; Manufacturer: Sullins Connector Solutions; Shrouded: N; Gender: Male; Row_Count: 2; RowSpacing_mm: 2.54
J10 = CMP-0077741-2: Header, 2.54mm, 3x2, Gold, R/A, TH; Manufacturer: Molex; Pitch_mm: 2.54; Gender: Male; Cert_UL: Y; Current_A: 3A; Voltage_V: 350V; Shrouded: N; Row_Count: 2
J11 = CMP-0055866-1: RJ45, 1.27mm, R/A, Gold, TH; Manufacturer: Stewart Connector; CNHeader: FALSE; Gender: Female; Row_Count: 2; RowSpacing_mm: 2.54; Pitch_mm: 1.27; CT: TRUE; Cert_UL: Y
J12 = CMP-0054991-1: JACK, SMA, 50 Ohm, Gold, R/A, TH; Manufacturer: TE Connectivity; CNHeader: FALSE; Gender: Female; CT: TRUE
J13 = CMP-0075484-1: Header, 100mil, 3x1, Gold, TH; Manufacturer: Samtec; Green_REACh: Passed; CT: False; Green_Lifecycle: Active; CNHeader: True
J14 J16-J18 = CMP-0075483-1: Header, 100mil, 2x1, Gold, TH; Manufacturer: Samtec; Green_REACh: Passed; CT: False; Green_Lifecycle: Active; CNHeader: True
J15 = CMP-0054990-1: SMA Straight PCB Socket Die Cast, 50 Ohm, TH; Manufacturer: TE Connectivity; CNHeader: FALSE; Green_Lifecycle: Active; Green_REACh: Passed; CT: TRUE
LD2-LD4 = CMP-0002917-1: as LD1 on sheet HSDC045A_Power
R9-R18 = CMP-0026822-3: RES, 0, 5%, 0.063 W, AEC-Q200 Grade 0, 0402; Manufacturer: Vishay-Dale; Power_W: 63mW; TempCo: 200 ppm/C; Value_Code: 0000; Value: 0; EIA_Code: E24; SizeX_mm: 1; SizeY_mm: 0.5; SizeZ_mm: 0.6; Value2: 0.063W; CompType: Resistor; AEC Qualified: Y; VDC_V: 50V; AEC Category: Q200
R19 R27 = CMP-0026822-3: RES, 0, 5%, 0.063 W, AEC-Q200 Grade 0, 0402; Manufacturer: Vishay-Dale; Power_W: 63mW; TempCo: 200 ppm/C; Value_Code: 0000; Value: 0; EIA_Code: E24; SizeX_mm: 1; SizeY_mm: 0.5; SizeZ_mm: 0.6; Value2: 0.063W; AEC Qualified: Y; VDC_V: 50V; AEC Category: Q200
R20 = CMP-0026890-5: RES, 2.2 k, 5%, 0.063 W, AEC-Q200 Grade 0, 0402; Manufacturer: Vishay-Dale; Power_W: 63mW; TempCo: 200 ppm/C; Value_Code: 2k20; Value: 2.2k; EIA_Code: E24; SizeX_mm: 1; SizeY_mm: 0.5; SizeZ_mm: 0.6; Value2: 0.063W; AEC Qualified: Y; VDC_V: 50V; AEC Category: Q200; AEC Grade: 0
R21 = CMP-0026515-2: RES, 6.49 k, 1%, 0.063 W, AEC-Q200 Grade 0, 0402; Manufacturer: Vishay-Dale; Power_W: 63mW; TempCo: 100 ppm/C; Value_Code: 6k49; Value: 6.49k; EIA_Code: E96; SizeX_mm: 1; SizeY_mm: 0.5; SizeZ_mm: 0.6; Value2: 0.063W; CompType: Resistor; AEC Qualified: Y; VDC_V: 50V; AEC Category: Q200; AEC Grade: 0
R22 = CMP-0027010-2: RES, 2.2 k, 5%, 0.05 W, 0201; Manufacturer: Vishay-Dale; Value: 2.2k; Value_Code: 2k20; Power_W: 50mW; Value2: 0.05W; VDC_V: 30V; TempCo: 200 ppm/C; EIA_Code: E24; AEC Category: Q200; AEC Qualified: N; SizeArea_mm2: 0.18; SizeX_mm: 0.6; SizeY_mm: 0.3; SizeZ_mm: 0.26
R23-R26 = CMP-0021425-3: RES, 75.0, 1%, 0.125 W, AEC-Q200 Grade 0, 0805; Manufacturer: Vishay-Dale; Power_W: 125mW; TempCo: 100 ppm/C; Value_Code: 75R0; Value: 75.0; EIA_Code: E96; Res_ohm: 75; SizeX_mm: 2; SizeY_mm: 1.25; SizeZ_mm: 1.45; Value2: 0.125W; SizeArea_mm2: 2.5; AEC Qualified: Y; VDC_V: 150V; AEC Category: Q200; AEC Grade: 0
R28 R30 R32 = CMP-0026934-3: as R4 on sheet HSDC045A_Power
R29 R31 R36 R39 R40 R42 R43 = CMP-0026237-2: RES, 2.49 k, 1%, 0.063 W, AEC-Q200 Grade 0, 0402; Manufacturer: Vishay-Dale; Power_W: 63mW; TempCo: 100 ppm/C; Value_Code: 2k49; Value: 2.49k; EIA_Code: E96; SizeX_mm: 1; SizeY_mm: 0.5; SizeZ_mm: 0.6; Value2: 0.063W; AEC Qualified: Y; VDC_V: 50V; AEC Grade: 0; AEC Category: Q200
R33 R38 R41 = CMP-0027011-4: RES, 0, 5%, 0.05 W, AEC-Q200 Grade 1, 0201; Manufacturer: Panasonic; Value: 0; Value_Code: 0000; Power_W: 50mW; Value2: 0.05W; VDC_V: 15V; TempCo: 600 ppm/C; EIA_Code: E24; AEC Category: Q200; AEC Grade: 1; AEC Qualified: Y; SizeArea_mm2: 0.18; SizeX_mm: 0.6; SizeY_mm: 0.3; SizeZ_mm: 0.26; SizeAreaWB_mm2: 2.08
R34 R35 = CMP-0016535-2: RES, 1.00 M, 1%, 1 W, 2010; Manufacturer: Stackpole Electronics Inc; Power_W: 1W; TempCo: 50 ppm/C; Value_Code: 1M00; U/M: EA; Value: 1.00Meg; EIA_Code: E96; Res_ohm: 1M; SizeX_mm: 5; SizeY_mm: 2.5; SizeZ_mm: 1.66; SizeArea_mm2: 12.5; AEC Qualified: N; VDC_V: 2kV; AEC Category: Q200
R37 = CMP-0026727-1: RES, 1.00 M, 1%, 0.063 W, 0402; Manufacturer: Yageo America; Value: 1.00Meg; Res_ohm: 1M; Value_Code: 1M00; Power_W: 63mW; Value2: 0.063W; TempCo: 100 ppm/C; EIA_Code: E96; U/M: EA; AEC Category: Q200; SizeArea_mm2: 0.5; SizeX_mm: 1; SizeZ_mm: 0.6
S1 = CMP-0002170-2: Switch, Normally open, 2.3N force, 200k operations, SMD; Manufacturer: C&K Components; Circuit: SPST Switch; VDC_V: 32V; SwitchFunction: Off-Mom; PositionCount: 1; CurrentRating_mA: 1.001kA
T2 = CMP-0030426-3: Transformer, 350 uH, SMT; Manufacturer: Pulse Engineering; Green_Lifecycle: Not Set; Green_REACh: Incomplete; Value: 350uH; Lp: 350; Ind_H: 350µH
U2 = CMP-0073613-3: 4-Channel Ultra-Low-Capacitance IEC ESD Protection Diode, DQA0010A (USON-10); Alternate Manufacturer: Texas Instruments; Green_Lifecycle: Active; SizeAreaWB_mm2: 7.0; Green_REACh: Passed; SizeZ_mm: 0.55; SizeX_mm: 1.0; SizeY_mm: 2.5; CompType: IC; AEC Category: Q200; AEC Qualified: N
U3 = CMP-0084215-1: DP83825IRMQR, RMQ0024A (WQFN-24); Alternate PartNumber: DP83825IRMQT; Alternate Manufacturer: Texas Instruments; SizeAreaWB_mm2: 16; SizeZ_mm: 0.8; SizeX_mm: 3; SizeArea_mm2: 9; CompType: IC; AEC Qualified: N; AEC Category: Q200
XTAL1 = CMP-0079863-1: Crystal, 25 MHz, 20 ppm, AEC-Q200 Grade 1, SMD; Manufacturer: ECS Inc.; TaMin_C: -55°C; Frequency Tolerance: 20 ppm; Frequency Stability: 50 ppm; SizeAreaWB_mm2: 14.7; Frequency_Fixed: 25MHz; TaMax_C: 125°C; SizeZ_mm: 0.8; SizeX_mm: 2.5; SizeY_mm: 3.2; SizeArea_mm2: 8; AEC Qualified: Y; AEC Grade: 1; AEC Category: Q200

## Sheet HSDC045A_Coms.SchDoc: Straps and MSP430
size 431 x 279 mm; Date: Not shown in title block; ApprovedBy: Not shown in title block; CheckedBy: Not shown in title block; Author: Not shown in title block; CompanyName: Not shown in title block; DrawnBy: Aniruddha Khadye; Engineer: Not shown in title block; Organization: Not shown in title block; Address1: Not shown in title block; Address2: Not shown in title block; Address3: Not shown in title block; Address4: Not shown in title block; DocumentNumber: 4; Revision: Use project parameter SCH_Rev; SheetNumber: 4; SheetTotal: 5; PageSetup: Record=PageOptions¦CenterHorizontal=True¦CenterVertical=True¦PrintScale=1.00¦XCorrection=1.00¦YCorrection=1.00¦PrintKind=0¦BorderSize=5000000¦LeftOffset=0¦BottomOffset=0¦Orientation=2¦PaperLength=1000¦PaperWidth=1000¦Scale=100¦PaperSource=15¦PrintQuality=600¦MediaType=1¦DitherType=10¦PaperKind=Letter¦PrintScaleMode=1
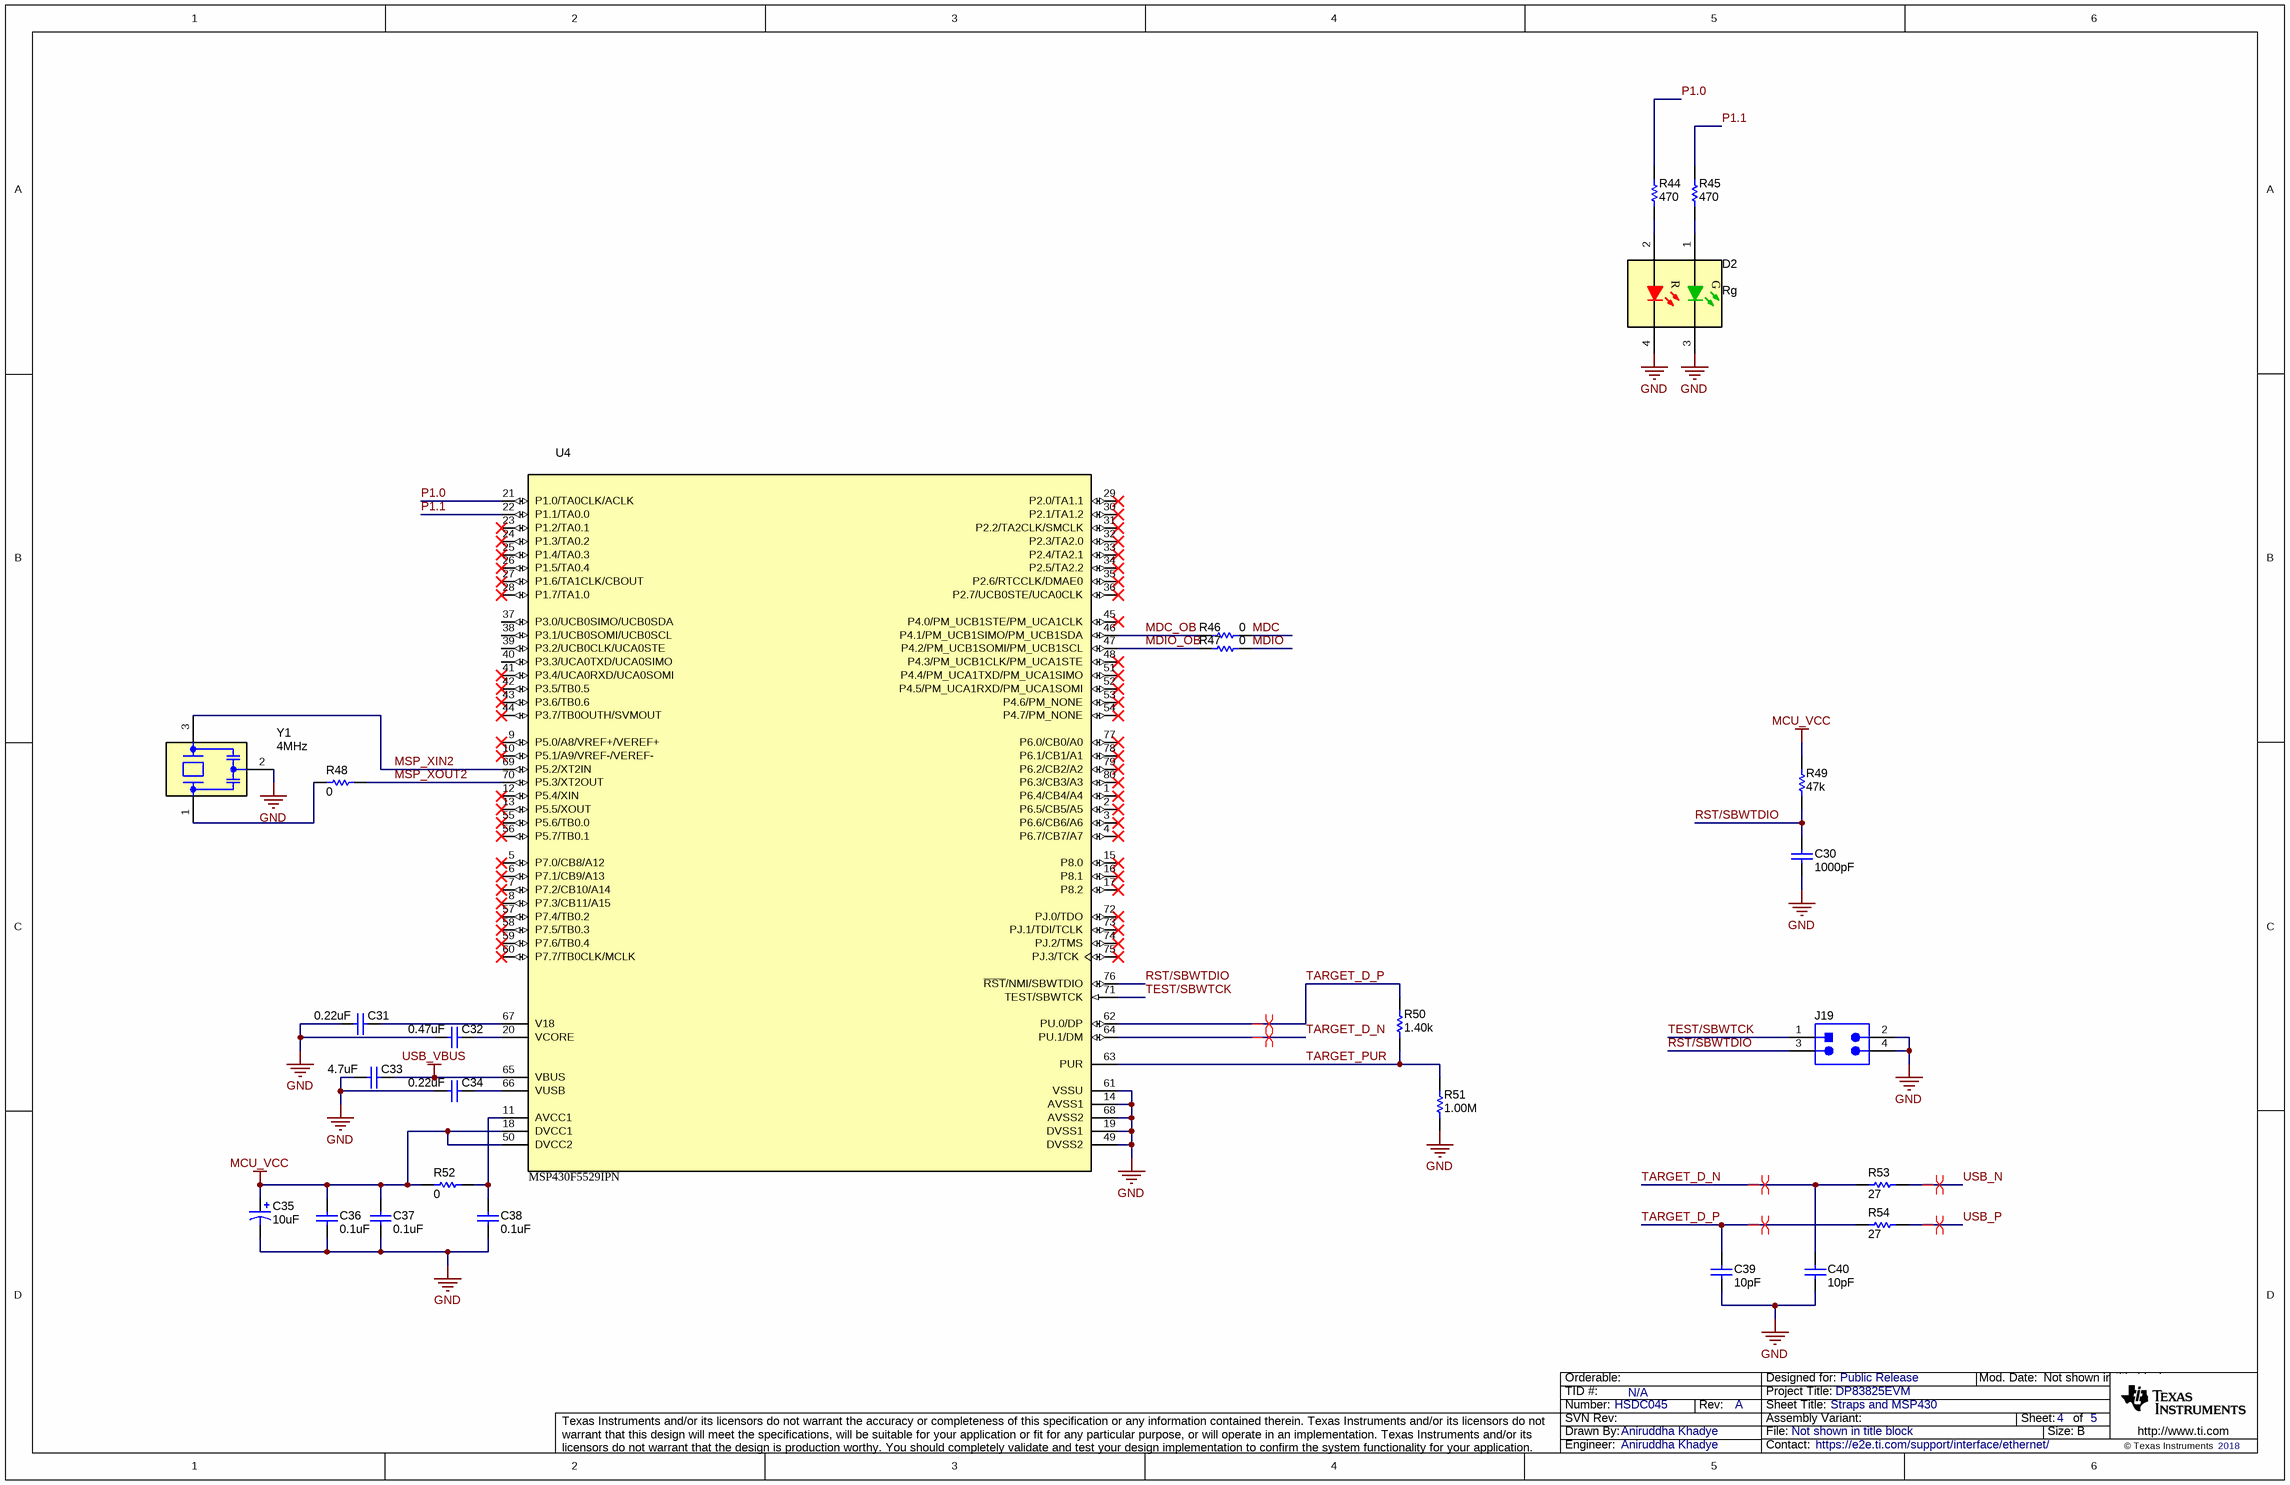
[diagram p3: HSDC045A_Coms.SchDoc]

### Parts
C30  ValueDisplayed: 1000pF  [0402]  (hidden comment: C1005NP01H102J050BA)
C31  ValueDisplayed: 0.22uF  [0603]  (hidden comment: C1608X5R1H224K080AB)
C32  ValueDisplayed: 0.47uF  [0603]  (hidden comment: C1608X6S1H474K080AB)
C33  ValueDisplayed: 4.7uF  [0603]  (hidden comment: C1608X5R1V475K080AC)
C34  ValueDisplayed: 0.22uF  [0603]  (hidden comment: C1608X5R1H224K080AB)
C35  ValueDisplayed: 10uF  [7343-31]  (hidden comment: TPSD106K035R0125)
C36  ValueDisplayed: 0.1uF  [0402]  (hidden comment: GRM155R71C104KA88D)
C37  ValueDisplayed: 0.1uF  [0402]  (hidden comment: GRM155R71C104KA88D)
C38  ValueDisplayed: 0.1uF  [0402]  (hidden comment: GRM155R71C104KA88D)
C39  ValueDisplayed: 10pF  [0603]  (hidden comment: CGA3E2NP01H100D080AA)
C40  ValueDisplayed: 10pF  [0603]  (hidden comment: CGA3E2NP01H100D080AA)
D2  value Rg  [HSMF-C165_RG]  (hidden comment: HSMF-C165)
J19  TSW-102-07-G-D  [TSW-102-07-G-D]  (value not drawn)
R44  ValueDisplayed: 470  [0201]  (hidden comment: RC0201JR-07470RL)
R45  ValueDisplayed: 470  [0201]  (hidden comment: RC0201JR-07470RL)
R46  ValueDisplayed: 0  [0201M]  (hidden comment: ERJ-1GE0R00C)
R47  ValueDisplayed: 0  [0201M]  (hidden comment: ERJ-1GE0R00C)
R48  ValueDisplayed: 0  [0402]  (hidden comment: CRCW04020000Z0ED)
R49  ValueDisplayed: 47k  [0402]  (hidden comment: CRCW040247K0JNED)
R50  ValueDisplayed: 1.40k  [0402]  (hidden comment: CRCW04021K40FKED)
R51  ValueDisplayed: 1.00M  [0402]  (hidden comment: CRCW04021M00FKED)
R52  ValueDisplayed: 0  [0402]  (hidden comment: CRCW04020000Z0ED)
R53  ValueDisplayed: 27  [0402]  (hidden comment: CRCW040227R0JNED)
R54  ValueDisplayed: 27  [0402]  (hidden comment: CRCW040227R0JNED)
U4  MSP430F5529IPN  [PN0080A_N]
Y1  Frequency_Fixed: 4MHz  [Murata_CSTCR_G15L]  (hidden comment: CSTCR4M00G15L99-R0)

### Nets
GND: C30.1 C31.2 C32.2 C33.1 C34.2 C35.2(-) C36.1 C37.1 C38.1 C39.1 C40.1 D2.3(K) D2.4(K) J19.2 J19.4 R51.2 U4.14(AVSS1) U4.19(DVSS1) U4.49(DVSS2) U4.61(VSSU) U4.68(AVSS2) Y1.2(GND)
MCU_VCC: C35.1(+) C36.2 C37.2 R49.1 R52.1 U4.18(DVCC1) U4.50(DVCC2)
USB_VBUS: C33.2 U4.65(VBUS)
MDC: R46.1
MDC_OB: R46.2 U4.46(P4.1/PM_UCB1SIMO/PM_UCB1SDA)
MDIO: R47.1
MDIO_OB: R47.2 U4.47(P4.2/PM_UCB1SOMI/PM_UCB1SCL)
MSP_XIN2: U4.69(P5.2/XT2IN) Y1.3(Out)
MSP_XOUT2: R48.2 U4.70(P5.3/XT2OUT)
P1.0: R44.2 U4.21(P1.0/TA0CLK/ACLK)
P1.1: R45.2 U4.22(P1.1/TA0.0)
RST/SBWTDIO: C30.2 J19.3 R49.2 U4.76(~{RST}/NMI/SBWTDIO)
TARGET_D_N: C40.2 R53.1 U4.64(PU.1/DM)
TARGET_D_P: C39.2 R50.2 R54.1 U4.62(PU.0/DP)
TARGET_PUR: R50.1 R51.1 U4.63(PUR)
TEST/SBWTCK: J19.1 U4.71(TEST/SBWTCK)
USB_N: R53.2
USB_P: R54.2
NetC31_1: C31.1 U4.67(V18)
NetC32_1: C32.1 U4.20(VCORE)
NetC34_1: C34.1 U4.66(VUSB)
NetC38_2: C38.2 R52.2 U4.11(AVCC1)
NetD2_1: D2.1(A) R45.1
NetD2_2: D2.2(A) R44.1
NetR48_1: R48.1 Y1.1(In)

Not connected (* = marked no-connect by the designer): U4 1(P6.4/CB4/A4)* 2(P6.5/CB5/A5)* 3(P6.6/CB6/A6)* 4(P6.7/CB7/A7)* 5(P7.0/CB8/A12)* 6(P7.1/CB9/A13)* 7(P7.2/CB10/A14)* 8(P7.3/CB11/A15)* 9(P5.0/A8/VREF+/VEREF+)* 10(P5.1/A9/VREF-/VEREF-)* 12(P5.4/XIN)* 13(P5.5/XOUT)* 15(P8.0)* 16(P8.1)* 17(P8.2)* 23(P1.2/TA0.1)* 24(P1.3/TA0.2)* 25(P1.4/TA0.3)* 26(P1.5/TA0.4)* 27(P1.6/TA1CLK/CBOUT)* 28(P1.7/TA1.0)* 29(P2.0/TA1.1)* 30(P2.1/TA1.2)* 31(P2.2/TA2CLK/SMCLK)* 32(P2.3/TA2.0)* 33(P2.4/TA2.1)* 34(P2.5/TA2.2)* 35(P2.6/RTCCLK/DMAE0)* 36(P2.7/UCB0STE/UCA0CLK)* 37(P3.0/UCB0SIMO/UCB0SDA) 38(P3.1/UCB0SOMI/UCB0SCL) 39(P3.2/UCB0CLK/UCA0STE) 40(P3.3/UCA0TXD/UCA0SIMO) 41(P3.4/UCA0RXD/UCA0SOMI)* 42(P3.5/TB0.5)* 43(P3.6/TB0.6)* 44(P3.7/TB0OUTH/SVMOUT)* 45(P4.0/PM_UCB1STE/PM_UCA1CLK)* 48(P4.3/PM_UCB1CLK/PM_UCA1STE)* 51(P4.4/PM_UCA1TXD/PM_UCA1SIMO)* 52(P4.5/PM_UCA1RXD/PM_UCA1SOMI)* 53(P4.6/PM_NONE)* 54(P4.7/PM_NONE)* 55(P5.6/TB0.0)* 56(P5.7/TB0.1)* 57(P7.4/TB0.2)* 58(P7.5/TB0.3)* 59(P7.6/TB0.4)* 60(P7.7/TB0CLK/MCLK)* 72(PJ.0/TDO)* 73(PJ.1/TDI/TCLK)* 74(PJ.2/TMS)* 75(PJ.3/TCK)* 77(P6.0/CB0/A0)* 78(P6.1/CB1/A1)* 79(P6.2/CB2/A2)* 80(P6.3/CB3/A3)*

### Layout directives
differential pair: TARGET_D_N, TARGET_D_P, USB_N, USB_P

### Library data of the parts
C30 = CMP-0006254-2: CAP, CERM, 1000 pF, 50 V, +/- 5%, C0G/NP0, 0402; Manufacturer: TDK; Polarized: N; Value: 1000pF; U/M: EA; Cap_F: 1nF; Value1: Unknown; VDC_V: 50V; TaMin_C: -55°C; TaMax_C: 150°C; SizeArea_mm2: 0.5; SizeAreaWB_mm2: 3; SizeX_mm: 1; SizeZ_mm: 0.6; AEC Category: Q200
C31 = CMP-0007013-5: CAP, CERM, 0.22 uF, 50 V, +/- 10%, X5R, 0603; Manufacturer: TDK; Polarized: N; Value: 0.22uF; U/M: EA; Cap_F: 220nF; ESR_ohm: 0.021699; Value1: 0.021699 ohm; VDC_V: 50V; IRMS_A: 1.12496A; TaMin_C: -55°C; TaMax_C: 85°C; SizeArea_mm2: 1.28; SizeAreaWB_mm2: 4.68; SizeX_mm: 1.6; SizeY_mm: 0.8; SizeZ_mm: 1; AEC Category: Q200
C32 = CMP-0007033-4: CAP, CERM, 0.47 uF, 50 V, +/- 10%, X6S, 0603; Manufacturer: TDK; Polarized: N; Value: 0.47uF; U/M: EA; Cap_F: 470nF; ESR_ohm: 0.010974; Value1: 0.010974 ohm; VDC_V: 50V; IRMS_A: 1.57483A; TaMin_C: -55°C; TaMax_C: 105°C; SizeArea_mm2: 1.28; SizeAreaWB_mm2: 4.68; SizeX_mm: 1.6; SizeY_mm: 0.8; SizeZ_mm: 1; AEC Category: Q200
C33 = CMP-0007022-5: CAP, CERM, 4.7 uF, 35 V, +/- 10%, X5R, 0603; Manufacturer: TDK; Polarized: N; CompType: Capacitor; Value: 4.7uF; U/M: EA; Cap_F: 4.7µF; ESR_ohm: 3.728m; Value1: 0.003728 ohm; VDC_V: 35V; IRMS_A: 2.69359A; TaMin_C: -55°C; TaMax_C: 85°C; SizeArea_mm2: 1.28; SizeAreaWB_mm2: 4.68; SizeX_mm: 1.6; SizeY_mm: 0.8; SizeZ_mm: 1; AEC Category: Q200
C34 = CMP-0007013-5: CAP, CERM, 0.22 uF, 50 V, +/- 10%, X5R, 0603; Manufacturer: TDK; Polarized: N; CompType: Capacitor; Value: 0.22uF; U/M: EA; Cap_F: 220nF; ESR_ohm: 0.021699; Value1: 0.021699 ohm; VDC_V: 50V; IRMS_A: 1.12496A; TaMin_C: -55°C; TaMax_C: 85°C; SizeArea_mm2: 1.28; SizeAreaWB_mm2: 4.68; SizeX_mm: 1.6; SizeY_mm: 0.8; SizeZ_mm: 1; AEC Category: Q200
C35 = CMP-0011855-2: CAP, TA, 10 uF, 35 V, +/- 10%, 0.125 ohm, SMD; Manufacturer: AVX; Polarized: Y; CompType: Capacitor; Value: 10uF; U/M: EA; Cap_F: 10µF; VDC_V: 35V; ESR_ohm: 1.25d; IRMS_A: 9.86dA; TaMin_C: -55°C; TaMax_C: 125°C; Cap_Case: D; AEC Category: Q200; SizeArea_mm2: 31.39; SizeAreaWB_mm2: 58.59; SizeX_mm: 7.3; SizeY_mm: 4.3; SizeZ_mm: 3.1
C36-C38 = CMP-0006641-2: as C2 on sheet HSDC045A_Power
C39 C40 = CMP-0007074-4: CAP, CERM, 10 pF, 50 V, +/- 5%, C0G/NP0, 0603; Manufacturer: TDK; Polarized: N; Value: 10pF; U/M: EA; Value1: Unknown; VDC_V: 50V; TaMin_C: -55°C; TaMax_C: 150°C; SizeArea_mm2: 1.28; SizeAreaWB_mm2: 4.68; SizeX_mm: 1.6; SizeY_mm: 0.8; SizeZ_mm: 1; AEC Category: Q200
D2 = CMP-0002934-2: LED, Rg, SMD; Manufacturer: Avago; Vf_V: 2.2V; Io_A: 20mA; Vr_V: 5V; Ir_A: 100µA; Tjmax_C: 85°C; Value1: W; LuminousIntensity_IV: 20; Angle: 120; U/M: EA
J19 = CMP-0075404-1: Header, 100mil, 2x2, Gold, TH; Manufacturer: Samtec; Pitch_mm: 2.54; Gender: Male; Shrouded: N; Row_Count: 2; Current_A: 6.3A; Voltage_V: 550V; Cert_CSA: Y; CNHeader: True; CT: False; Green_Lifecycle: Active; Green_REACh: Passed
R44 R45 = CMP-0027127-1: RES, 470, 5%, 0.05 W, 0201; Manufacturer: Yageo America; Power_W: 50mW; TempCo: 200 ppm/C; Value_Code: 470R; U/M: EA; Value: 470; EIA_Code: E24; SizeX_mm: 0.6; SizeY_mm: 0.3; SizeZ_mm: 0.26; Value2: 0.05W; SizeArea_mm2: 0.18; AEC Qualified: N; VDC_V: 25V; AEC Category: Q200
R46 R47 = CMP-0027011-4: as R33 on sheet HSDC045A_DP83825
R48 R52 = CMP-0026822-3: RES, 0, 5%, 0.063 W, AEC-Q200 Grade 0, 0402; Manufacturer: Vishay-Dale; Value: 0; Value_Code: 0000; Power_W: 63mW; Value2: 0.063W; VDC_V: 50V; TempCo: 200 ppm/C; EIA_Code: E24; AEC Category: Q200; AEC Qualified: Y; SizeArea_mm2: 0.5; SizeX_mm: 1; SizeZ_mm: 0.6
R49 = CMP-0026935-3: RES, 47 k, 5%, 0.063 W, AEC-Q200 Grade 0, 0402; Manufacturer: Vishay-Dale; Value: 47k; Value_Code: 47k0; Power_W: 63mW; Value2: 0.063W; VDC_V: 50V; TempCo: 200 ppm/C; EIA_Code: E24; AEC Category: Q200; AEC Qualified: Y; AEC Grade: 0; SizeArea_mm2: 0.5; SizeX_mm: 1; SizeZ_mm: 0.6
R50 = CMP-0026085-3: RES, 1.40 k, 1%, 0.063 W, AEC-Q200 Grade 0, 0402; Manufacturer: Vishay-Dale; Value: 1.40k; Res_ohm: 1.4k; Value_Code: 1k40; Power_W: 63mW; Value2: 0.063W; VDC_V: 50V; TempCo: 100 ppm/C; EIA_Code: E96; AEC Category: Q200; AEC Qualified: Y; AEC Grade: 0; SizeArea_mm2: 0.5; SizeX_mm: 1; SizeZ_mm: 0.6
R51 = CMP-0026100-2: RES, 1.00 M, 1%, 0.063 W, AEC-Q200 Grade 0, 0402; Manufacturer: Vishay-Dale; Value: 1.00Meg; Res_ohm: 1M; Value_Code: 1M00; Power_W: 63mW; Value2: 0.063W; VDC_V: 50V; TempCo: 100 ppm/C; EIA_Code: E96; AEC Category: Q200; AEC Qualified: Y; AEC Grade: 0; SizeArea_mm2: 0.5; SizeX_mm: 1; SizeZ_mm: 0.6
R53 R54 = CMP-0026888-3: RES, 27, 5%, 0.063 W, AEC-Q200 Grade 0, 0402; Manufacturer: Vishay-Dale; Value: 27; Value_Code: 27R0; Power_W: 63mW; Value2: 0.063W; VDC_V: 50V; TempCo: 200 ppm/C; EIA_Code: E24; AEC Category: Q200; AEC Qualified: Y; AEC Grade: 0; SizeArea_mm2: 0.5; SizeX_mm: 1; SizeZ_mm: 0.6
U4 = CMP-0038965-1: 25 MHz Mixed Signal Microcontroller with 128 KB Flash, 8192 B SRAM and 63 GPIOs, -40 to 85 degC, 80-pin QFP (PN), Green (RoHS & no Sb/Br); Manufacturer: Texas Instruments; ADC: 12-bit SAR; ADC Channels: 16; Brown Out Reset: Yes; DMA: 3; Flash(KB): 128; Frequency(MHz): 25; GPIO: 63; Multiplier: 32x32; SRAM(B): 8192; SubFamily: 5 Series; Timers - 16-bit: 4; USB: 1; USCI_A (UART/LIN/IrDA/SPI): 2
Y1 = CMP-0006148-5: Resonator, 4 MHz, 1000 ppm, 39 pF, SMD; Manufacturer: MuRata; SizeAreaWB_mm2: 16.5; SizeArea_mm2: 9; SizeX_mm: 4.5; SizeY_mm: 2; SizeZ_mm: 1.2; TaMin_C: 0°C; TaMax_C: 70°C; Frequency Stability: 800 ppm; AEC Category: Q200; AEC Qualified: N; Load Capacitance: 39 pF

## Sheet HSDC045A_Hardware.SchDoc: Hardware Page
size 431 x 279 mm; Date: Not shown in title block; ApprovedBy: Not shown in title block; CheckedBy: Not shown in title block; Author: Not shown in title block; CompanyName: Not shown in title block; DrawnBy: Aniruddha Khadye; Engineer: Not shown in title block; Organization: Not shown in title block; Address1: Not shown in title block; Address2: Not shown in title block; Address3: Not shown in title block; Address4: Not shown in title block; DocumentNumber: 5; Revision: Use project parameter SCH_Rev; SheetNumber: 5; SheetTotal: 5; PageSetup: Record=PageOptions¦CenterHorizontal=True¦CenterVertical=True¦PrintScale=1.00¦XCorrection=1.00¦YCorrection=1.00¦PrintKind=0¦BorderSize=5000000¦LeftOffset=0¦BottomOffset=0¦Orientation=2¦PaperLength=1000¦PaperWidth=1000¦Scale=100¦PaperSource=15¦PrintQuality=600¦MediaType=1¦DitherType=10¦PaperKind=Letter¦PrintScaleMode=1
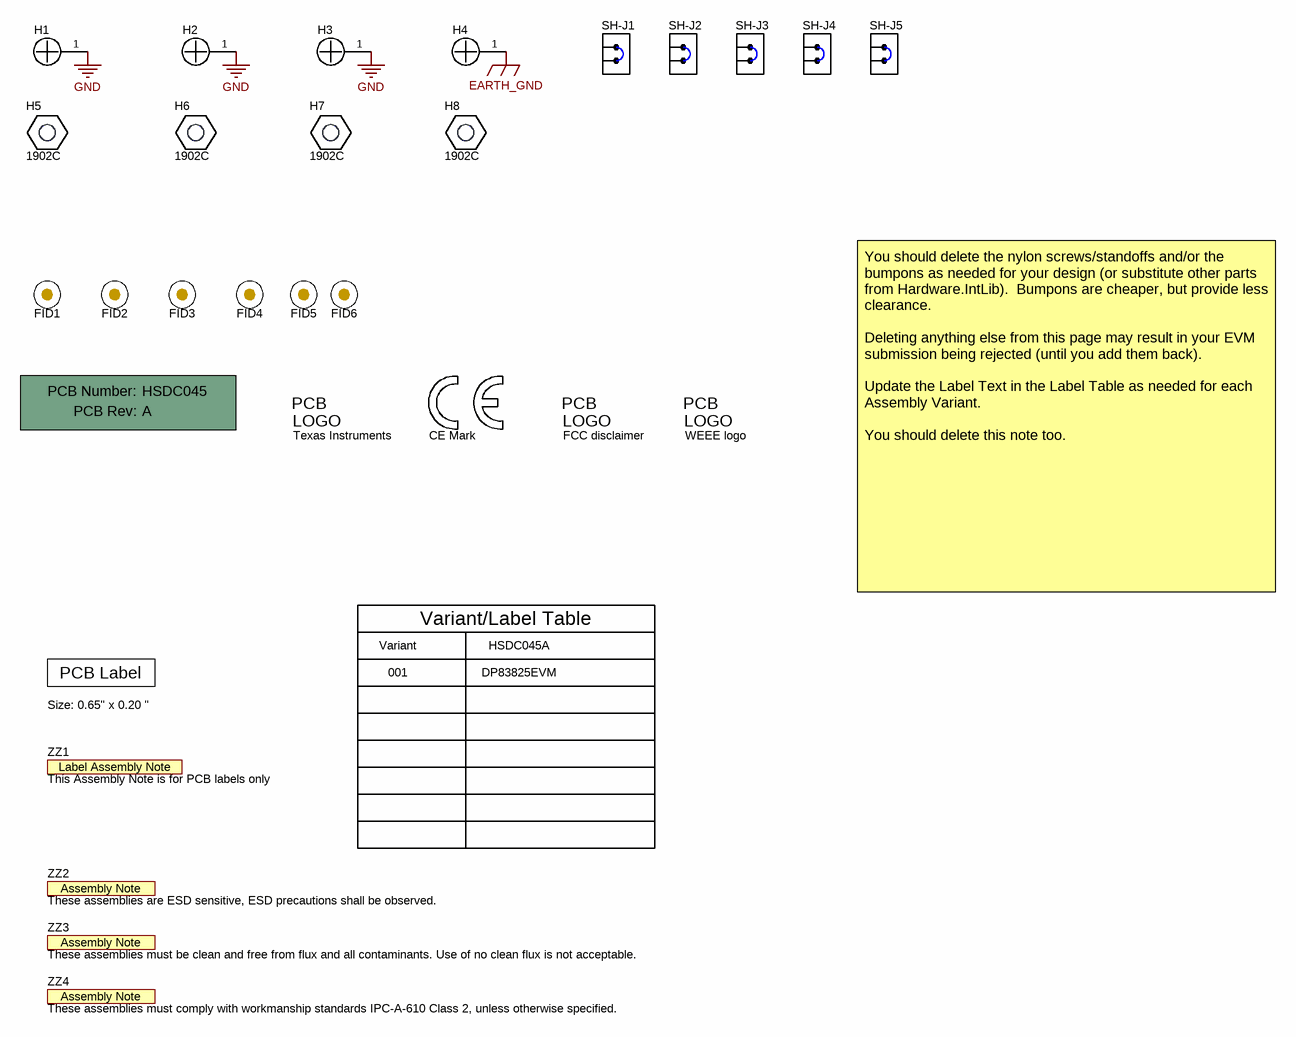
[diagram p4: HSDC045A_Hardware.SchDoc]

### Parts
!PCB1  Printed Circuit Board  (value not drawn)  (mechanical)
FID1  Fiducial  [Fiducial10-20]  (value not drawn)
FID2  Fiducial  [Fiducial10-20]  (value not drawn)
FID3  Fiducial  [Fiducial10-20]  (value not drawn)
FID4  Fiducial  [Fiducial10-20]  (value not drawn)
FID5  Fiducial  [Fiducial10-20]  (value not drawn)
FID6  Fiducial  [Fiducial10-20]  (value not drawn)
H1  NY PMS 440 0025 PH  [NY PMS 440 0025 PH]  (value not drawn)
H2  NY PMS 440 0025 PH  [NY PMS 440 0025 PH]  (value not drawn)
H3  NY PMS 440 0025 PH  [NY PMS 440 0025 PH]  (value not drawn)
H4  NY PMS 440 0025 PH  [NY PMS 440 0025 PH]  (value not drawn)
H5  1902C  [Keystone_1902C]
H6  1902C  [Keystone_1902C]
H7  1902C  [Keystone_1902C]
H8  1902C  [Keystone_1902C]
LBL1  Note: Size: 0.65" x 0.20 "  [Label_650x200]  (hidden comment: THT-14-423-10)
Logo1  CE Mark  [CE_Mark_5mm]  (no BOM)
Logo2  Texas Instruments  [TI_Stacked_Overlay_Small]  (no BOM)
Logo3  FCC disclaimer  [FCC_disclaimer]  (no BOM)
Logo4  WEEE logo  [WEEE_Minimum]  (no BOM)
SH-J1  M7582-05  [Harwin_M7582-05]  (value not drawn)
SH-J2  M7582-05  [Harwin_M7582-05]  (value not drawn)
SH-J3  M7582-05  [Harwin_M7582-05]  (value not drawn)
SH-J4  M7582-05  [Harwin_M7582-05]  (value not drawn)
SH-J5  M7582-05  [Harwin_M7582-05]  (value not drawn)
ZZ1  This Assembly Note is for PCB labels only  [AssemblyNoteLabel]  (no BOM)
ZZ2  These assemblies are ESD sensitive, ESD precautions shall be observed.  [AssemblyNote]  (no BOM)
ZZ3  These assemblies must be clean and free from flux and all contaminants. Use of no clean flux is not acceptable.  [AssemblyNote]  (no BOM)
ZZ4  These assemblies must comply with workmanship standards IPC-A-610 Class 2, unless otherwise specified.  [AssemblyNote]  (no BOM)

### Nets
EARTH_GND: H4.1
GND: H1.1 H2.1 H3.1

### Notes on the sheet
- Variant
- Variant/Label Table
- HSDC045A
- You should delete the nylon screws/standoffs and/or the bumpons as needed for your design (or substitute other parts from Hardware.IntLib).  Bumpons are cheaper, but provide less clearance.
  Deleting anything else from this page may result in your EVM submission being rejected (until you add them back).
  Update the Label Text in the Label Table as needed for each Assembly Variant.
  You should delete this note too.
- 001
- DP83825EVM

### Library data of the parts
!PCB1 = CMP-0003618-2: Manufacturer: Any; PartNumber: HSDC045; CompType: PCB
FID1-FID6 = CMP-0077181-1: Fiducial mark.  There is nothing to buy or mount.
H1-H4 = CMP-0003617-1: Machine Screw, Round, #4-40 x 1/4, Nylon, Philips panhead; Manufacturer: B&F Fastener Supply; CompType: Hardware
H5-H8 = CMP-0003610-1: Standoff, Hex, 0.5"L #4-40 Nylon; Manufacturer: Keystone; CompType: Hardware
LBL1 = CMP-0003625-1: Thermal Transfer Printable Labels, 0.650" W x 0.200" H - 10,000 per roll; Manufacturer: Brady; CompType: Label
Logo1 = CMP-0074844-1: SymbolCreator: a0412235
Logo2 = CMP-0074838-1: Texas Instrument Corporate Signature; SymbolCreator: a0412235; Lib Reference: TI_Logo; Library Reference: Logo
Logo3 = CMP-0074847-1: FCC_disclaimer; Library Reference: Logo
Logo4 = CMP-0074769-1
SH-J1-SH-J5 = CMP-0078738-1: Single Operation 2.54mm Pitch Open Top Jumper Socket; Manufacturer: Harwin
ZZ1 = CMP-0003616-3
ZZ2 = CMP-0077236-1
ZZ3 = CMP-0077237-1
ZZ4 = CMP-0077238-1

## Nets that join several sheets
EARTH_GND: HSDC045A_DP83825 (8 pins), HSDC045A_Hardware (H4.1)
GND: HSDC045A_Power (23 pins), HSDC045A_DP83825 (53 pins), HSDC045A_Coms (22 pins), HSDC045A_Hardware (H1.1 H2.1 H3.1)
MCU_VCC: HSDC045A_Power (J5.2), HSDC045A_Coms (7 pins)
USB_VBUS: HSDC045A_Power (C1.1 C2.2 J1.1 J2.1), HSDC045A_Coms (C33.2 U4.65)
VDDA3P3: HSDC045A_Power (J3.2), HSDC045A_DP83825 (7 pins)
VDDIO: HSDC045A_Power (J4.2), HSDC045A_DP83825 (10 pins)
VFX: HSDC045A_Power (R8.1), HSDC045A_DP83825 (J10.2)
MDC: HSDC045A_DP83825 (R18.1 U3.16), HSDC045A_Coms (R46.1)
MDIO: HSDC045A_DP83825 (R19.1 R20.1 U3.15), HSDC045A_Coms (R47.1)
USB_N: HSDC045A_Power (J1.2), HSDC045A_Coms (R53.2)
USB_P: HSDC045A_Power (J1.3), HSDC045A_Coms (R54.2)

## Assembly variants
001: not fitted C14 C16 C18 C20 C27 C28 FID1 FID2 FID3 FID4 FID5 FID6 R5 R30 R34 R35 R36 R37 R41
